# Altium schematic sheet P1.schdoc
size 432 x 279 mm; Symbol: Drawing-Symbol_A4; @Project Name: esp32_devboard; @Page Count: 1; @Update Date: 2026-06-12; @Create Date: 2026-04-07; @Schematic Name: Schematic1; @Page No: 1; @Page Name: P1; Company: ECE.FR; Version: V3; Page Size: B; Drawn: Virgile B.; @Create Time: 14:29:46; @Update Time: 12:25:46; Border: 1; Width: 1700; Height: 1100; Region Start: 1; X Region Count: 6; Y Region Count: 4; Blade Width: 10; Title Block Position: 3; @Board Name: Board1; Device: Drawing-Symbol_A4
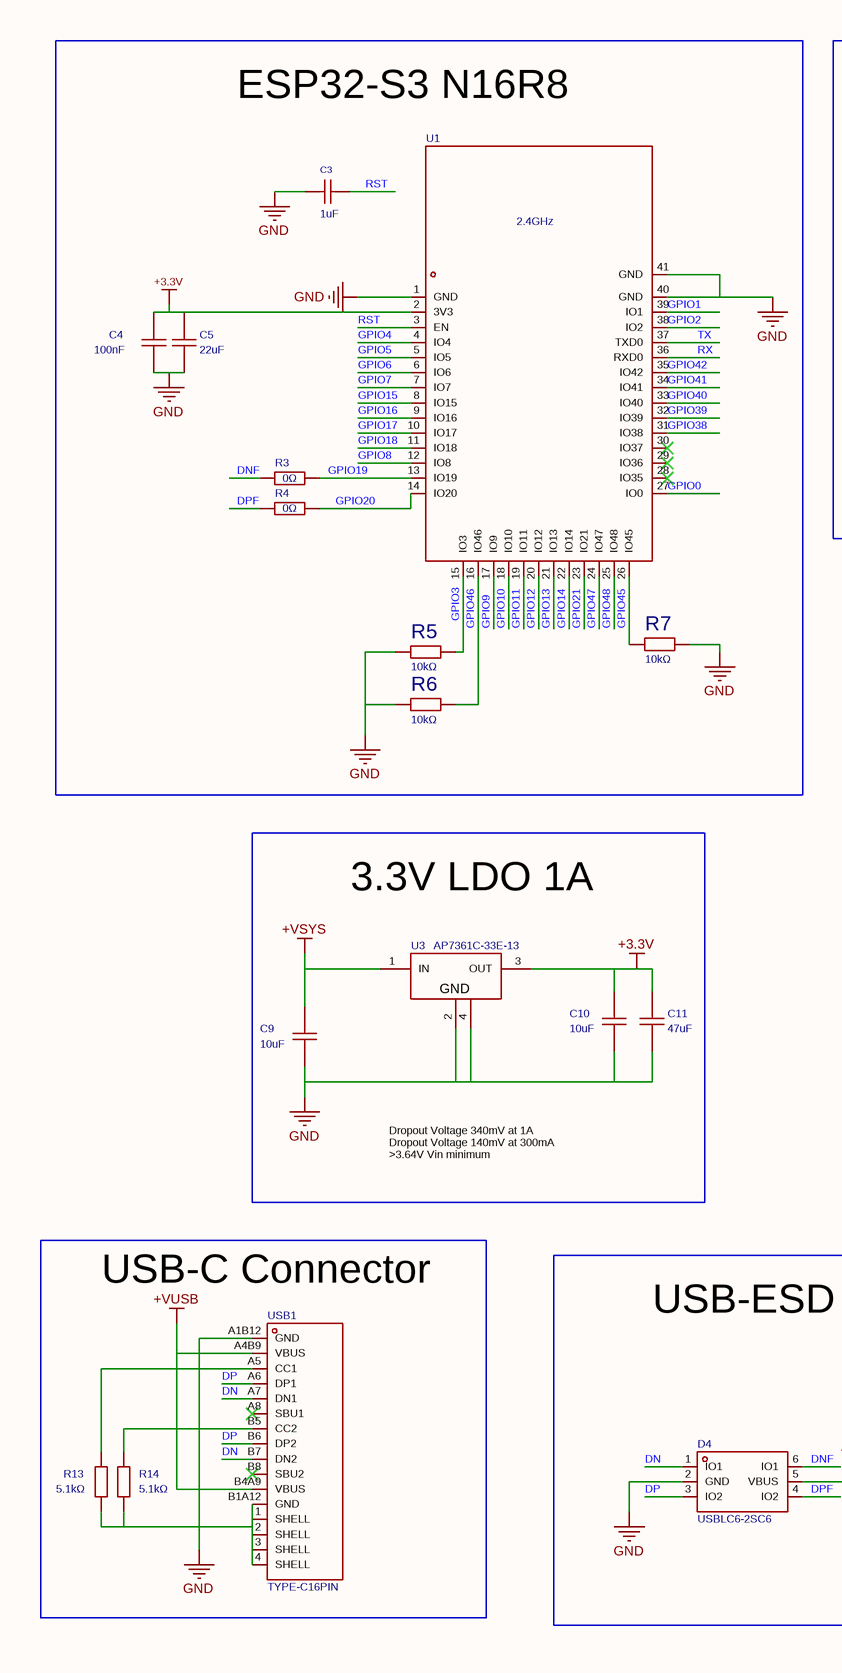
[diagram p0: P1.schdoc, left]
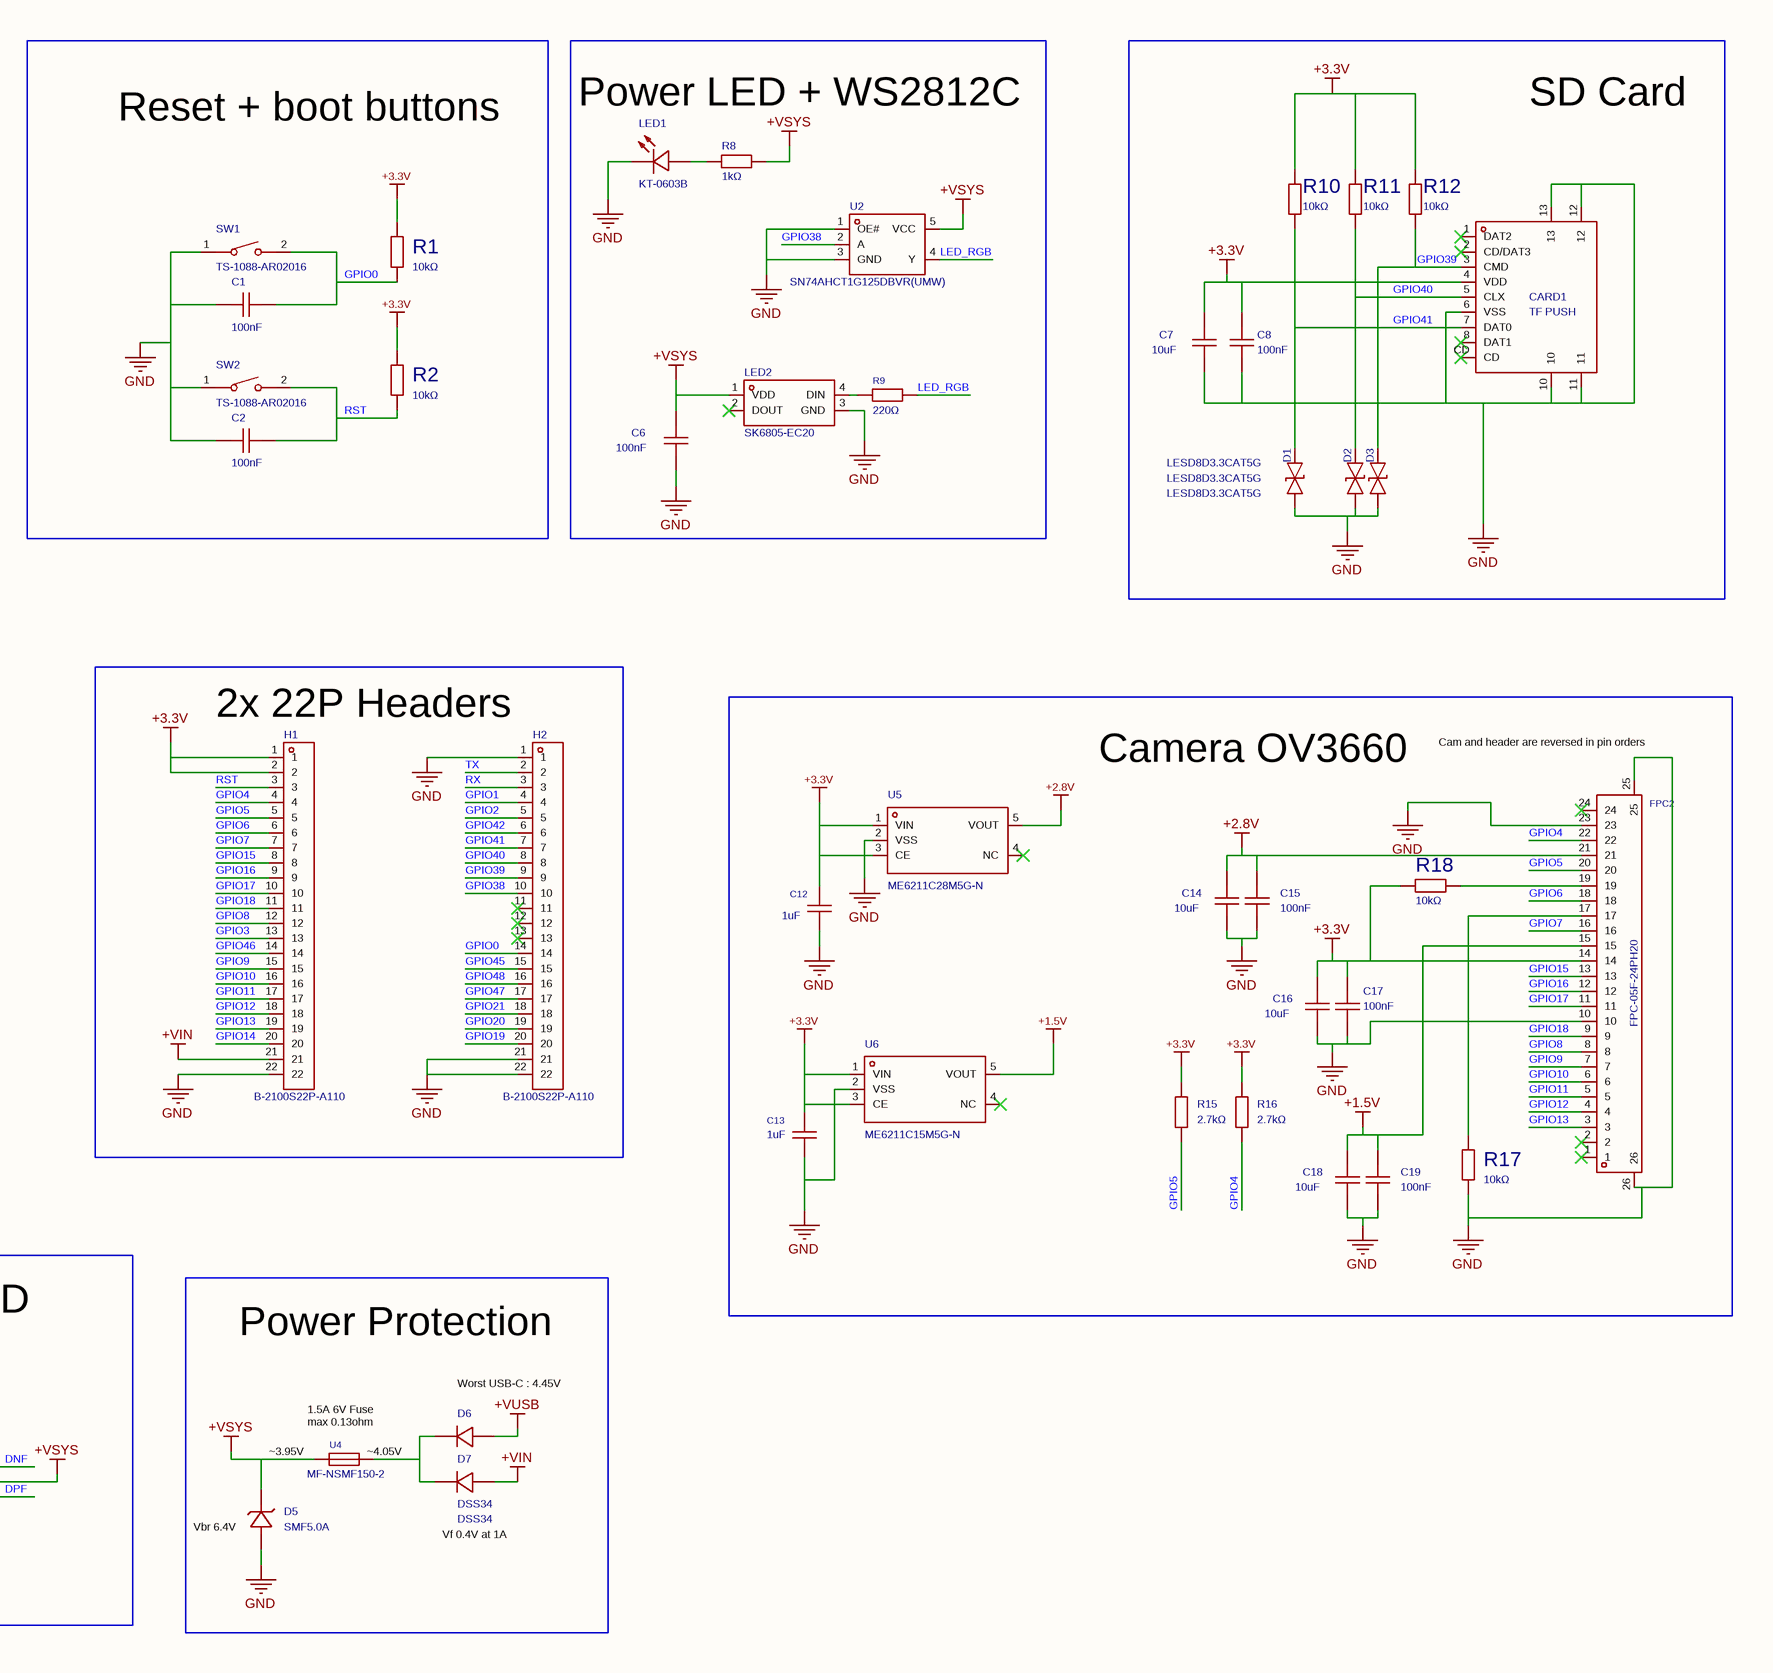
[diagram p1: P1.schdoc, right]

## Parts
C1  100nF  [C0603]
C2  100nF  [C0603]
C3  1uF  [C0805]
C4  100nF  [C0603]
C5  22uF  [C0805]
C6  100nF  [C0603]
C7  10uF  [C0805]
C8  100nF  [C0603]
C9  10uF  [C0805]
C10  10uF  [C0805]
C11  47uF  [C1206]
C12  1uF  [C0805]
C13  1uF  [C0805]
C14  10uF  [C0805]
C15  100nF  [C0603]
C16  10uF  [C0805]
C17  100nF  [C0603]
C18  10uF  [C0805]
C19  100nF  [C0603]
CARD1  TF PUSH  [TF-SMD_TF-PUSH]
D1  LESD8D3.3CAT5G  [SOD-882_L1.0-W0.6-BI]
D2  LESD8D3.3CAT5G  [SOD-882_L1.0-W0.6-BI]
D3  LESD8D3.3CAT5G  [SOD-882_L1.0-W0.6-BI]
D4  USBLC6-2SC6  [SOT-23-6_L2.9-W1.6-P0.95-LS2.8-BL]
D5  SMF5.0A  [SOD-123FL_L2.7-W1.8-LS3.8-RD]
D6  DSS34  [SOD-123_L2.8-W1.8-LS3.7-RD-2]
D7  DSS34  [SOD-123_L2.8-W1.8-LS3.7-RD-2]
FPC2  FPC-05F-24PH20  [FPC-SMD_24P-P0.50_FPC-05F-24PH20]
H1  B-2100S22P-A110  [HDR-TH_22P-P2.54-V-M]
H2  B-2100S22P-A110  [HDR-TH_22P-P2.54-V-M]
LED1  KT-0603B  [LED0603-RD]
LED2  SK6805-EC20  [LED-SMD_4P-L2.0-W2.0-BR]
R1  10kΩ  [R0603]
R2  10kΩ  [R0603]
R3  value 0Ω  [R0603]
R4  value 0Ω  [R0603]
R5  10kΩ  [R0603]
R6  10kΩ  [R0603]
R7  10kΩ  [R0603]
R8  1kΩ  [R0402]
R9  220Ω  [R0402]
R10  10kΩ  [R0603]
R11  10kΩ  [R0603]
R12  10kΩ  [R0603]
R13  5.1kΩ  [R0603]
R14  5.1kΩ  [R0603]
R15  2.7kΩ  [R0603]
R16  2.7kΩ  [R0603]
R17  10kΩ  [R0603]
R18  10kΩ  [R0603]
SW1  TS-1088-AR02016  [SW-SMD_L3.9-W3.0-P4.45]
SW2  TS-1088-AR02016  [SW-SMD_L3.9-W3.0-P4.45]
U1  2.4GHz  [WIRELM-SMD_ESP32-S3-WROOM-1]
U2  SN74AHCT1G125DBVR(UMW)  [SOT-23-5_L3.0-W1.5-P0.95-LS2.8-BL]
U3  AP7361C-33E-13  [SOT-223_L6.5-W3.5-P2.30-LS7.0-BR]
U4  MF-NSMF150-2  [F1206]
U5  ME6211C28M5G-N  [SOT-23-5_L3.0-W1.7-P0.95-LS2.8-BR]
U6  ME6211C15M5G-N  [SOT-23-5_L3.0-W1.7-P0.95-LS2.8-BR]
USB1  TYPE-C16PIN  [USB-C-SMD_TYPE-C16PIN]

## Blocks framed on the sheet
ESP32-S3 N16R8: C3-C5 R3-R7 U1
Reset + boot buttons: C1 C2 R1 R2 SW1 SW2
Power LED + WS2812C: C6 LED1 LED2 R8 R9 U2
SD Card: C7 C8 CARD1 D1-D3 R10-R12
2x 22P Headers: H1 H2
Camera OV3660: C12-C19 FPC2 R15-R18 U5 U6
3.3V LDO 1A: C9-C11 U3
USB-C Connector: R13 R14 USB1
USB-ESD: D4
Power Protection: D5-D7 U4

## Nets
+1.5V: C18.1 C19.1 FPC2.15 U6.5(VOUT)
+2.8V: C14.1 C15.1 FPC2.21 U5.5(VOUT)
+3.3V: C4.2 C5.2 C7.1 C8.1 C10.1 C11.2 C12.2 C13.2 C16.1 C17.1 CARD1.4(VDD) FPC2.14 H1.1 H1.2 R1.2 R2.2 R10.1 R11.1 R12.1 R15.2 R16.2 R18.2 U1.2(3V3) U3.3(OUT) U5.1(VIN) U5.3(CE) U6.1(VIN) U6.3(CE)
+VIN: D7.2(A) H1.21
+VSYS: C6.2 C9.1 D4.5(VBUS) D5.1(K) LED2.1(VDD) R8.2 U2.5(VCC) U3.1(IN) U4.1
+VUSB: D6.2(A) USB1.A4B9(VBUS) USB1.B4A9(VBUS)
GND: C1.2 C2.2 C3.1 C4.1 C5.1 C6.1 C7.2 C8.2 C9.2 C10.2 C11.1 C12.1 C13.1 C14.2 C15.2 C16.2 C17.2 C18.2 C19.2 CARD1.6(VSS) CARD1.10 CARD1.11 CARD1.12 CARD1.13 D1.1 D2.1 D3.1 D4.2(GND) D5.2(A) FPC2.10 FPC2.23 FPC2.25 FPC2.26 H1.22 H2.1 H2.21 H2.22 LED1.1(K) LED2.3(GND) R5.2 R6.2 R7.1 R13.1 R14.1 R17.2 SW1.1 SW2.1 U1.1(GND) U1.40(GND) U1.41(GND) U2.1(OE#) U2.3(GND) U3.2(GND) U3.4(GND) U5.2(VSS) U6.2(VSS) USB1.1(SHELL) USB1.2(SHELL) USB1.3(SHELL) USB1.4(SHELL) USB1.A1B12(GND) USB1.B1A12(GND)
DN: D4.1(IO1) USB1.A7(DN1) USB1.B7(DN2)
DNF: D4.6(IO1) R3.1
DP: D4.3(IO2) USB1.A6(DP1) USB1.B6(DP2)
DPF: D4.4(IO2) R4.1
GPIO0: C1.1 H2.14 R1.1 SW1.2 U1.27(IO0)
GPIO1: H2.4 U1.39(IO1)
GPIO2: H2.5 U1.38(IO2)
GPIO3: H1.13 R5.1 U1.15(IO3)
GPIO4: FPC2.22 H1.4 R16.1 U1.4(IO4)
GPIO5: FPC2.20 H1.5 R15.1 U1.5(IO5)
GPIO6: FPC2.18 H1.6 U1.6(IO6)
GPIO7: FPC2.16 H1.7 U1.7(IO7)
GPIO8: FPC2.8 H1.12 U1.12(IO8)
GPIO9: FPC2.7 H1.15 U1.17(IO9)
GPIO10: FPC2.6 H1.16 U1.18(IO10)
GPIO11: FPC2.5 H1.17 U1.19(IO11)
GPIO12: FPC2.4 H1.18 U1.20(IO12)
GPIO13: FPC2.3 H1.19 U1.21(IO13)
GPIO14: H1.20 U1.22(IO14)
GPIO15: FPC2.13 H1.8 U1.8(IO15)
GPIO16: FPC2.12 H1.9 U1.9(IO16)
GPIO17: FPC2.11 H1.10 U1.10(IO17)
GPIO18: FPC2.9 H1.11 U1.11(IO18)
GPIO19: H2.20 R3.2 U1.13(IO19)
GPIO20: H2.19 R4.2 U1.14(IO20)
GPIO21: H2.18 U1.23(IO21)
GPIO38: H2.10 U1.31(IO38) U2.2(A)
GPIO39: CARD1.3(CMD) D3.2 H2.9 R12.2 U1.32(IO39)
GPIO40: CARD1.5(CLX) D2.2 H2.8 R11.2 U1.33(IO40)
GPIO41: CARD1.7(DAT0) D1.2 H2.7 R10.2 U1.34(IO41)
GPIO42: H2.6 U1.35(IO42)
GPIO45: H2.15 R7.2 U1.26(IO45)
GPIO46: H1.14 R6.1 U1.16(IO46)
GPIO47: H2.17 U1.24(IO47)
GPIO48: H2.16 U1.25(IO48)
LED_RGB: R9.2 U2.4(Y)
RST: C2.1 C3.2 H1.3 R2.1 SW2.2 U1.3(EN)
RX: H2.3 U1.36(RXD0)
TX: H2.2 U1.37(TXD0)
NetD6_1: D6.1(C) D7.1(C) U4.2
NetFPC2_17: FPC2.17 R17.1
NetFPC2_19: FPC2.19 R18.1
NetLED1_2: LED1.2(A) R8.1
NetLED2_4: LED2.4(DIN) R9.1
NetR13_2: R13.2 USB1.A5(CC1)
NetR14_2: R14.2 USB1.B5(CC2)

Not connected (* = marked no-connect by the designer): CARD1 1(DAT2)* 2(CD/DAT3)* 8(DAT1)* CD*; FPC2 1* 2* 24*; H2 11* 12* 13*; LED2 2(DOUT)*; U1 28(IO35)* 29(IO36)* 30(IO37)*; U5 4(NC)*; U6 4(NC)*; USB1 A8(SBU1)* B8(SBU2)*

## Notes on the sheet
- (near FPC2) Cam and header are reversed in pin orders
- Dropout Voltage 340mV at 1A
  Dropout Voltage 140mV at 300mA
  >3.64V Vin minimum
- (near D6) Worst USB-C : 4.45V
- ~3.95V
- 1.5A 6V Fuse
  max 0.13ohm
- (near U4) ~4.05V
- (near D5) Vbr 6.4V
- (near D7) Vf 0.4V at 1A

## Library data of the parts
C1 C2 C4 C6 C8 C15 C17 C19 = CC0603KRX7R9BB104: Capacitance:100nF Tolerance:±10% Tolerance:±10% Voltage Rating:50V Temperature Coefficient:X7R; Manufacturer: YAGEO(国巨); AddInBom: yes; ModelId: 624118aa3cc7497086c383c2d72e0852; ModelName: C0603_L1.6-W0.8-H0.8; ModelTransform: 62.992,31.496,0,0,0,0,0,0,0; Tolerance: ±10%; Voltage Rating: 50V; Temperature Coefficient: X7R
C3 C12 C13 = CL21B105KBFNNNE: Capacitance:1uF Tolerance:±10% Tolerance:±10% Voltage Rating:50V Temperature Coefficient:X7R; Manufacturer: SAMSUNG(三星); AddInBom: yes; ModelId: 8c88e81f49c6409b980720ec8953afb6; ModelName: C0805_L2.0-W1.3-H1.3; ModelTransform: 78.74,51.181,0,0,0,0,0,0.0005,0; Tolerance: ±10%; Voltage Rating: 50V; Temperature Coefficient: X7R
C5 = CL21A226MAQNNNE: Capacitance:22uF Tolerance:±20% Tolerance:±20% Voltage Rating:25V Temperature Coefficient:X5R; Manufacturer: SAMSUNG(三星); AddInBom: yes; ModelId: 8c88e81f49c6409b980720ec8953afb6; ModelName: C0805_L2.0-W1.3-H1.3; ModelTransform: 78.74,51.181,0,0,0,0,0,0.0005,0; Tolerance: ±20%; Voltage Rating: 25V; Temperature Coefficient: X5R
C7 C9 C10 C14 C16 C18 = GRM21BR61H106KE43L: Capacitance:10uF Tolerance:±10% Tolerance:±10% Voltage Rating:50V Temperature Coefficient:X5R; Manufacturer: muRata(村田); AddInBom: yes; ModelId: 8c88e81f49c6409b980720ec8953afb6; ModelName: C0805_L2.0-W1.3-H1.3; ModelTransform: 78.74,51.181,0,0,0,0,0,0.0005,0; Tolerance: ±10%; Voltage Rating: 50V; Temperature Coefficient: X5R
C11 = GRM31CR61C476ME44L: Capacitance:47uF Tolerance:±20% Tolerance:±20% Voltage Rating:16V Temperature Coefficient:X5R; Manufacturer: muRata(村田); AddInBom: yes; ModelId: c6790e9475e1483991d2c64340b24e96; ModelName: C1206_L3.2-W1.6-H1.3; ModelTransform: 125.984,62.992,0,0,0,0,0,0,0; Tolerance: ±20%; Voltage Rating: 16V; Temperature Coefficient: X5R
CARD1 = TF PUSH: Card Connection Mode:Push-Push Card Type:MicroSD Card (TF Card) Connector Type:Connector and Ejector Additional Card Detection Pins:No Supplementary Features:- Height Above Board:2mm Operating Temperature:-25℃~+90℃ Operating Temperature:-25℃~+90℃; Manufacturer: SHOU HAN(首韩); AddInBom: yes; ModelId: 38fe85a3a7ce4fbea215a86a16fcc74b; ModelTransform: 635.826,598.424,0,0,0,0,0.002,-82.441,-23.622; Additional Card Detection Pins: No
D1-D3 = LESD8D3.3CAT5G_C172409: Polarity:Bidirectional Reverse Stand-Off Voltage (Vrwm):3.3V Clamping Voltage:10V Peak Pulse Current (Ipp):9A Peak Pulse Power Dissipation (Ppp):60W Voltage - Breakdown:6.5V Reverse Leakage Current (Ir):100nA level of protection:IEC 61000-4-2 Type:ESD Jun; Manufacturer: LRC(乐山无线电); AddInBom: yes; ModelId: 2f5b2d11927d4638911a47235b7a7532; ModelName: WBFBP-03E_L1.0-W0.6-P0.64-BL; ModelTransform: 40.1574,23.622,0,0,0,0,0,0,0; Reverse Stand-Off Voltage (Vrwm): 3.3V; Clamping Voltage: 10V; Peak Pulse Current (Ipp): 9A; Peak Pulse Power Dissipation (Ppp): 60W; Voltage - Breakdown: 6.5V; Reverse Leakage Current (Ir): 100nA; Type: ESD; Junction Capacitance: 16pF
D4 = USBLC6-2SC6_C2827654: Polarity:Unidirectional Reverse Stand-Off Voltage (Vrwm):5V Clamping Voltage:12V Peak Pulse Current (Ipp):6A Peak Pulse Power Dissipation (Ppp):150W Voltage - Breakdown:6V Reverse Leakage Current (Ir):80nA Number of Channels:2 Operating Temperature:-55℃~+; Manufacturer: TECH PUBLIC(台舟); Check: true; AddInBom: yes; ModelId: 1370be37a17e44418ae52e2b4cc1f5e5; ModelName: SOT-23-6_L2.9-W1.6-H1.5-LS2.8-P0.95; ModelTransform: 110.236,113.364,0,90,0,0,0.0005,0.0005,0; Reverse Stand-Off Voltage (Vrwm): 5V; Clamping Voltage: 12V; Peak Pulse Current (Ipp): 6A; Peak Pulse Power Dissipation (Ppp): 150W; Voltage - Breakdown: 6V; Reverse Leakage Current (Ir): 80nA; Number of Channels: 2; level of protection: IEC 61000-4-2；IEC 61000-4-4；IEC 61000-4-5; Type: ESD; Junction Capacitance: 0.35pF
D5 = SMF5.0A_C19077497: Polarity:Unidirectional Reverse Stand-Off Voltage (Vrwm):5V Clamping Voltage:9.2V Peak Pulse Current (Ipp):21.7A@10/1000us Peak Pulse Power Dissipation (Ppp):200W@10/1000us Voltage - Breakdown:7V Reverse Leakage Current (Ir):400uA Number of Channels:1 Ope; Manufacturer: R+O(宏嘉诚); AddInBom: yes; ModelId: e3993ae174574c859a842f4a900fcd6c; ModelName: SOD-123FL_L2.8-W1.8-H1.1-LS3.6; ModelTransform: 141.732,70.866,0,180,0,0,0,0,0; Reverse Stand-Off Voltage (Vrwm): 5V; Clamping Voltage: 9.2V; Voltage - Breakdown: 7V; Reverse Leakage Current (Ir): 400uA; Number of Channels: 1; level of protection: IEC 61000-4-2; Type: TVS
D6 D7 = DSS34_C2923958: Diode Configuration:Independent Voltage - Forward(Vf@If):550mV@3A Voltage - DC Reverse(Vr):40V Current - Rectified:3A Reverse Leakage Current (Ir):500uA@40V Operating Junction Temperature Range:-55℃~+125℃ Operating Junction Temperature Range:-55℃~+125℃ No; Manufacturer: CJ(江苏长电/长晶); AddInBom: yes; ModelId: 560a7cf99d0e44cb9af362aaf5d7923d; ModelName: SOD-123_L2.8-W1.8-LS3.7-RD; ModelTransform: 144.8816,62.992,0,0,0,0,0,0,0; Voltage - DC Reverse(Vr): 40V; Current - Rectified: 3A; Non-Repetitive Peak Forward Surge Current: 70A
FPC2 = FPC-05F-24PH20: Locking Feature:Hinged Lid Contact Type:Surface Mount Number of Contacts:24P Pitch:0.5mm Mounting Type:Bottom Contact FFC, FCB Thickness:0.3mm FFC, FCB Thickness:0.3mm Height Above Board:2mm Contact Material:Phosphor Bronze Contact Plating:Tin Operating T; Manufacturer: XUNPU(讯普); AddInBom: yes; ModelId: 39b6f87f694b4e5ca6c0d21fa6e92623; ModelTransform: 645.668,201.5744,0,0,0,0,-0.003,-47.244,0; Number of Contacts: 24P; Pitch: 0.5mm; FFC, FCB Thickness: 0.3mm; Rated Voltage (Max): 50V; Current Rating (Max): 500mA
H1 H2 = B-2100S22P-A110: Pin Structure:1x22P Pitch:2.54mm Circluar Pins/Square Pins:Pin Header Mounting Type:Through Hole Number of Rows:1 Number of Pins:22P Current Rating:3A Voltage Rating (Max):250V Length of Mating Pin:6mm Insulation Height:2.5mm Length of End Connection Pin:; Manufacturer: Ckmtw(灿科盟); AddInBom: yes; ModelId: 9190b9663644491da8d3a4f0d6abead9; ModelName: HDR-TH_22P-P2.54-M-LI-1X22P; ModelTransform: 2199.99552,98.425,0,0,0,0,0,0,-118.11; Pin Structure: 1x22P; Pitch: 2.54mm; Current Rating: 3A; Voltage Rating (Max): 250V
LED1 = KT-0603B: Lamp Holder Type:- Illumination Color:Blue Voltage - Forward(Vf):3.1V Voltage - Forward(Vf):3.1V Power(Watts):100mW Forward Current:5mA Wavelength - Dominant:460nm~475nm Wavelength - Dominant:460nm~475nm Peak Wavelength:469nm Diode Configuration:Discrete; Manufacturer: KENTO; Symbol: Blue light 0603; AddInBom: yes; ModelId: 5e3b568068dd46cf8019c1d1baa0031b; ModelTransform: 63.7794,32.283,0,0,0,0,0,0,0; Illumination Color: Blue; Voltage - Forward(Vf): 3.1V; Power(Watts): 100mW; Forward Current: 5mA; Peak Wavelength: 469nm; Diode Configuration: Discrete Diode; Lens Color: Water Clear; Luminous Intensity: 175mcd; Viewing Angle: 120°
LED2 = SK6805-EC20: Wavelength:620nm~630nm；520nm~535nm；460nm~475nm Operating Temperature:-40℃~+80℃; Manufacturer: 欧思科光电; AddInBom: yes; ModelId: 3dfe11bcc24c497a845d12a775090ce3; ModelTransform: 78.74,78.74,0,0,0,0,0,0,0
R1 R2 R5-R7 R10-R12 R17 R18 = 0603WAF1002T5E: Type:Thick Film Resistor Resistance:10kΩ Tolerance:±1% Tolerance:±1% Power(Watts):100mW Voltage-Supply(Max):75V Temperature Coefficient:±100ppm/℃ Temperature Coefficient:±100ppm/℃ Operating Temperature:-55℃~+155℃ Operating Temperature:-55℃~+155℃; Manufacturer: UNI-ROYAL(厚声); AddInBom: yes; ModelId: 112863783b5b41f1b5254f87eedc7932; ModelTransform: 31.8897,63.7794,0,90,0,0,0,0,0; Tolerance: ±1%; Power(Watts): 100mW; Voltage-Supply(Max): 75V
R3 R4 = 0603WAF0000T5E: Temperature Coefficient:- Temperature Coefficient:- Tolerance: Resistance: Power(Watts): Overload Voltage (Max): Operating Temperature Range: Operating Temperature Range:; Manufacturer: UNI-ROYAL(厚声); AddInBom: yes; ModelId: 3281a289d46d4bb1877be1eabd090e13; ModelName: R0603_L1.6-W0.8-H0.8; ModelTransform: 62.992,31.496,0,0,0,0,0,0,0
R8 = 0402WGF1001TCE: Type:Thick Film Resistor Resistance:1kΩ Tolerance:±1% Tolerance:±1% Power(Watts):62.5mW Voltage-Supply(Max):50V Temperature Coefficient:±100ppm/℃ Temperature Coefficient:±100ppm/℃ Operating Temperature:-55℃~+155℃ Operating Temperature:-55℃~+155℃; Manufacturer: UNI-ROYAL(厚声); AddInBom: yes; ModelId: efdecb7dae4442949d28eecaf748420f; ModelName: R0402_L1.0-W0.5-H0.4; ModelTransform: 39.37,19.685,0,0,0,0,0,0,0; Tolerance: ±1%; Power(Watts): 62.5mW; Voltage-Supply(Max): 50V
R9 = 0402WGF2200TCE: Type:Thick Film Resistor Resistance:220Ω Tolerance:±1% Tolerance:±1% Power(Watts):62.5mW Voltage-Supply(Max):50V Temperature Coefficient:±100ppm/℃ Temperature Coefficient:±100ppm/℃ Operating Temperature:-55℃~+155℃ Operating Temperature:-55℃~+155℃; Manufacturer: UNI-ROYAL(厚声); AddInBom: yes; ModelId: efdecb7dae4442949d28eecaf748420f; ModelName: R0402_L1.0-W0.5-H0.4; ModelTransform: 39.37,19.685,0,0,0,0,0,0,0; Tolerance: ±1%; Power(Watts): 62.5mW; Voltage-Supply(Max): 50V
R13 R14 = 0603WAF5101T5E: Type:Thick Film Resistor Resistance:5.1kΩ Tolerance:±1% Tolerance:±1% Power(Watts):100mW Voltage-Supply(Max):75V Temperature Coefficient:±100ppm/℃ Temperature Coefficient:±100ppm/℃ Operating Temperature:-55℃~+155℃ Operating Temperature:-55℃~+155℃; Manufacturer: UNI-ROYAL(厚声); AddInBom: yes; ModelId: 112863783b5b41f1b5254f87eedc7932; ModelTransform: 31.8897,63.7794,0,90,0,0,0,0,0; Tolerance: ±1%; Power(Watts): 100mW; Voltage-Supply(Max): 75V
R15 R16 = 0603WAF2701T5E: Type:Thick Film Resistor Resistance:2.7kΩ Tolerance:±1% Tolerance:±1% Power(Watts):100mW Voltage-Supply(Max):75V Temperature Coefficient:±100ppm/℃ Temperature Coefficient:±100ppm/℃ Operating Temperature:-55℃~+155℃ Operating Temperature:-55℃~+155℃; Manufacturer: UNI-ROYAL(厚声); AddInBom: yes; ModelId: 112863783b5b41f1b5254f87eedc7932; ModelTransform: 31.8897,63.7794,0,90,0,0,0,0,0; Tolerance: ±1%; Power(Watts): 100mW; Voltage-Supply(Max): 75V
SW1 SW2 = TS-1088-AR02016: Circuit:SPST Actuator Style:Round Button Operating Force:1.6N Mounting Type:Surface Mount,Vertical Length:4mm Width:3mm Switch Height:2mm with Bracket:Without Bracket Contact Current:50mA Voltage Rating:12V Actuator/Cap Color:Black Termination Style:SMD(S; Manufacturer: XUNPU(讯普); AddInBom: yes; ModelId: 305d1c5953df46c2be38ec48c2aa1876; ModelName: SW-SMD_L3.9-W2.9-H2.0-LS4.8; ModelTransform: 188.976,114.174,0,0,0,0,0,0,0; Circuit: SPST; Operating Force: 1.6N; Switch Height: 2mm; Contact Current: 50mA; Voltage Rating: 12V; Actuator/Cap Color: Black; Life: 100,000 Cycles
U1 = ESP32-S3-WROOM-1-N16R8: Utilized IC / Part:ESP32-S3R8 Interface Type:I2C；GPIO；UART；SPI；USB；I2S Frequency:2.4GHz Antenna Type:On-board PCB Antenna Output Power:20.5dBm Output Power:20.5dBm Voltage - Supply:3V~3.6V Voltage - Supply:3V~3.6V Receive  Current:95mA Send  Current:355mA; Manufacturer: ESPRESSIF(乐鑫); Symbol: ESP32-S3-WROOM-1(N16R8); AddInBom: yes; ModelId: dbf21c799c1c42a38df84fd714a1a1c8; ModelTransform: 708.73866,1003.97437,0,0,0,0,0,143.7,0; Receive  Current: 95mA; Send  Current: 355mA; Sensitivity: -103.5dBm
U2 = SN74AHCT1G125DBVR(UMW): Logic Type:- Number of Channels:1 Voltage - Supply:4.5V~5.5V Voltage - Supply:4.5V~5.5V Quiescent Current:10uA Current - Output Low(IOL):8mA Current - Output High(IOH):8mA Input Logic Level - High:2V Input Logic Level - High:2V Input Logic Level - Low:800; Manufacturer: UMW(友台半导体); AddInBom: yes; ModelId: cebaa11776a44c29af77b00c76af25b8; ModelTransform: 118.11,110.236,0,0,0,0,0,0,0; Number of Channels: 1; Quiescent Current: 10uA; Current - Output Low(IOL): 8mA; Input Logic Level - High: 2V; Input Logic Level - Low: 800mV; Output Logic Level - High: 4.4V；3.8V; Output Logic Level - Low: 440mV; Propagation Delay: 12ns@5V,50pF
U3 = AP7361C-33E-13: Output Configuration:Positive Voltage - Supply:6V Output Voltage:3.3V Output Voltage:3.3V Output Current:1A Power Supply Rejection Ratio (PSRR):75dB@(1kHz) Voltage Dropout:340mV@(1A) standby current:80uA Noise:- Features:Thermal shutdown；Enable control；Sh; Manufacturer: DIODES(美台); AddInBom: yes; ModelId: e5f8b32b785646b6abbef6d5ae2fe0600819f05c4eef4c71ace90d822a990e87; ModelName: SOT-223-4P_L6.5-W3.5-H1.6-LS7.0-P2.30; ModelTransform: 279.89794,255.905,0,180,0,0,0.0005,0.0005,0; Voltage - Supply: 6V; Output Voltage: 3.3V; standby current: 80uA; Output Type: Fixed; Number of Outputs: 1
U4 = MF-NSMF150-2: Voltage - Max:6V Current - Max:- Hold Current:- Trip Current:- Power Dissipation:600mW Resistance - Initial (Ri) (Min):30mΩ Resistance - Post Trip (R1) (Max):130mΩ Time to Trip(Max):- Operating Temperature:-40℃~+85℃ Operating Temperature:-40℃~+85℃ Length:; Manufacturer: BOURNS; AddInBom: yes; ModelId: 61372169742747e19cbd4ac5ee5e48b1; ModelName: F1206_L3.2-W1.7-H0.6; ModelTransform: 125.984,66.929,0,0,0,0,0,0,0; Voltage - Max: 6V; Power Dissipation: 600mW; Resistance - Initial (Ri) (Min): 30mΩ; Resistance - Post Trip (R1) (Max): 130mΩ
U5 = ME6211C28M5G-N: Output Type:Fixed Voltage - Supply:6V Output Voltage:2.8V Output Voltage:2.8V Output Current:450mA Power Supply Rejection Ratio (PSRR):70dB@(1kHz) Voltage Dropout:220mV@(200mA) standby current:55uA Noise:50uVrms Features:Enable Operating Temperature:-40℃~; Manufacturer: MICRONE(南京微盟); AddInBom: yes; ModelId: 3168b22659ce4998ae232d44bb704e0a; ModelName: SOT-23-5_L2.9-W1.6-H1.1-LS2.8-P0.95; ModelTransform: 114.173,109.636,0,180,0,0,0,0,0; Output Type: Fixed; Voltage - Supply: 6V; Output Voltage: 2.8V; Output Current: 450mA; standby current: 55uA; Output Configuration: Positive; Number of Outputs: 1
U6 = ME6211C15M5G-N_C53100: Output Type:Fixed Voltage - Supply:6V Output Voltage:1.5V Output Voltage:1.5V Output Current:300mA Power Supply Rejection Ratio (PSRR):70dB@(1kHz) Voltage Dropout:- standby current:- Noise:- Features:Enable Operating Temperature:-40℃~+85℃ Operating Temper; Manufacturer: MICRONE(南京微盟); AddInBom: yes; ModelId: 3168b22659ce4998ae232d44bb704e0a; ModelName: SOT-23-5_L2.9-W1.6-H1.1-LS2.8-P0.95; ModelTransform: 114.173,109.636,0,180,0,0,0,0,0; Output Type: Fixed; Voltage - Supply: 6V; Output Voltage: 1.5V; Output Current: 300mA; Output Configuration: Positive; Number of Outputs: 1
USB1 = TYPE-C16PIN: Connector Type:Type-C Protocol Standard:- Gender:Female Mounting Type:Surface Mount, Right Angle Number of Contacts:16P Number of Ports:1 Current Rating-Power:3A Voltage Rating:30V Connect-Disconnect Life:10,000 Cycles Supplementary Features:- Center Heig; Manufacturer: SHOU HAN(首韩); AddInBom: yes; ModelId: 319e90d785004510b337af202e3d530e; ModelTransform: 351.9678,311.023,0,180,0,0,0,-41.85,-39.37; Connector Type: Type-C; Gender: Female; Number of Contacts: 16P; Number of Ports: 1; Current Rating-Power: 3A; Voltage Rating: 30V; Detection color: Black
